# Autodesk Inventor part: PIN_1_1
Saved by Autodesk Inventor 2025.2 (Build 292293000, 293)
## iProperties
Created: 2025-04
Part Number: PIN_1_1
Material: Generic
Description: NOT SPECIFIED
Document SubType Name: Modeling
Designer: BennF
Density: 1 g/cm^3
Appearance: Default
Author: BennF
Revision Number: 2LAST_VERSION
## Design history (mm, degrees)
feature "Base1"
body "Solid1"
